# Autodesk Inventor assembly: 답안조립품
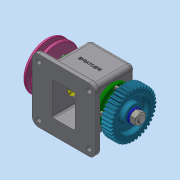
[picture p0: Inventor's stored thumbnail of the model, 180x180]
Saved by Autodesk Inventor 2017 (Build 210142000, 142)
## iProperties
Part Number: 답안조립품
Material: 일반
Document SubType Name: Assembly
Designer: MRC
Author: MRC
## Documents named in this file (12)
- C:\Users\MRC\Desktop\720706V1007\답안조립품.iam
- C:\Users\MRC\Desktop\720706V1007\본체.ipt
- C:\Users\MRC\Desktop\720706V1007\베어링 6204.ipt
- C:\Users\MRC\Desktop\720706V1007\커버.ipt
- C:\Users\MRC\Desktop\720706V1007\볼트 M4x0.7.ipt
- C:\Users\MRC\Desktop\720706V1007\축.ipt
- C:\Users\MRC\Desktop\720706V1007\키 5x5.ipt
- C:\Users\MRC\Desktop\720706V1007\V벨트풀리.ipt
- C:\Users\MRC\Desktop\720706V1007\오일실 20x35x8.ipt
- C:\Users\MRC\Desktop\720706V1007\와셔 12x24.ipt
- C:\Users\MRC\Desktop\720706V1007\너트 M12x1.25.ipt
- C:\Users\MRC\Desktop\720706V1007\스퍼기어.ipt
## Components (1 placed, 1 different names)
1. V벨트풀리:1
